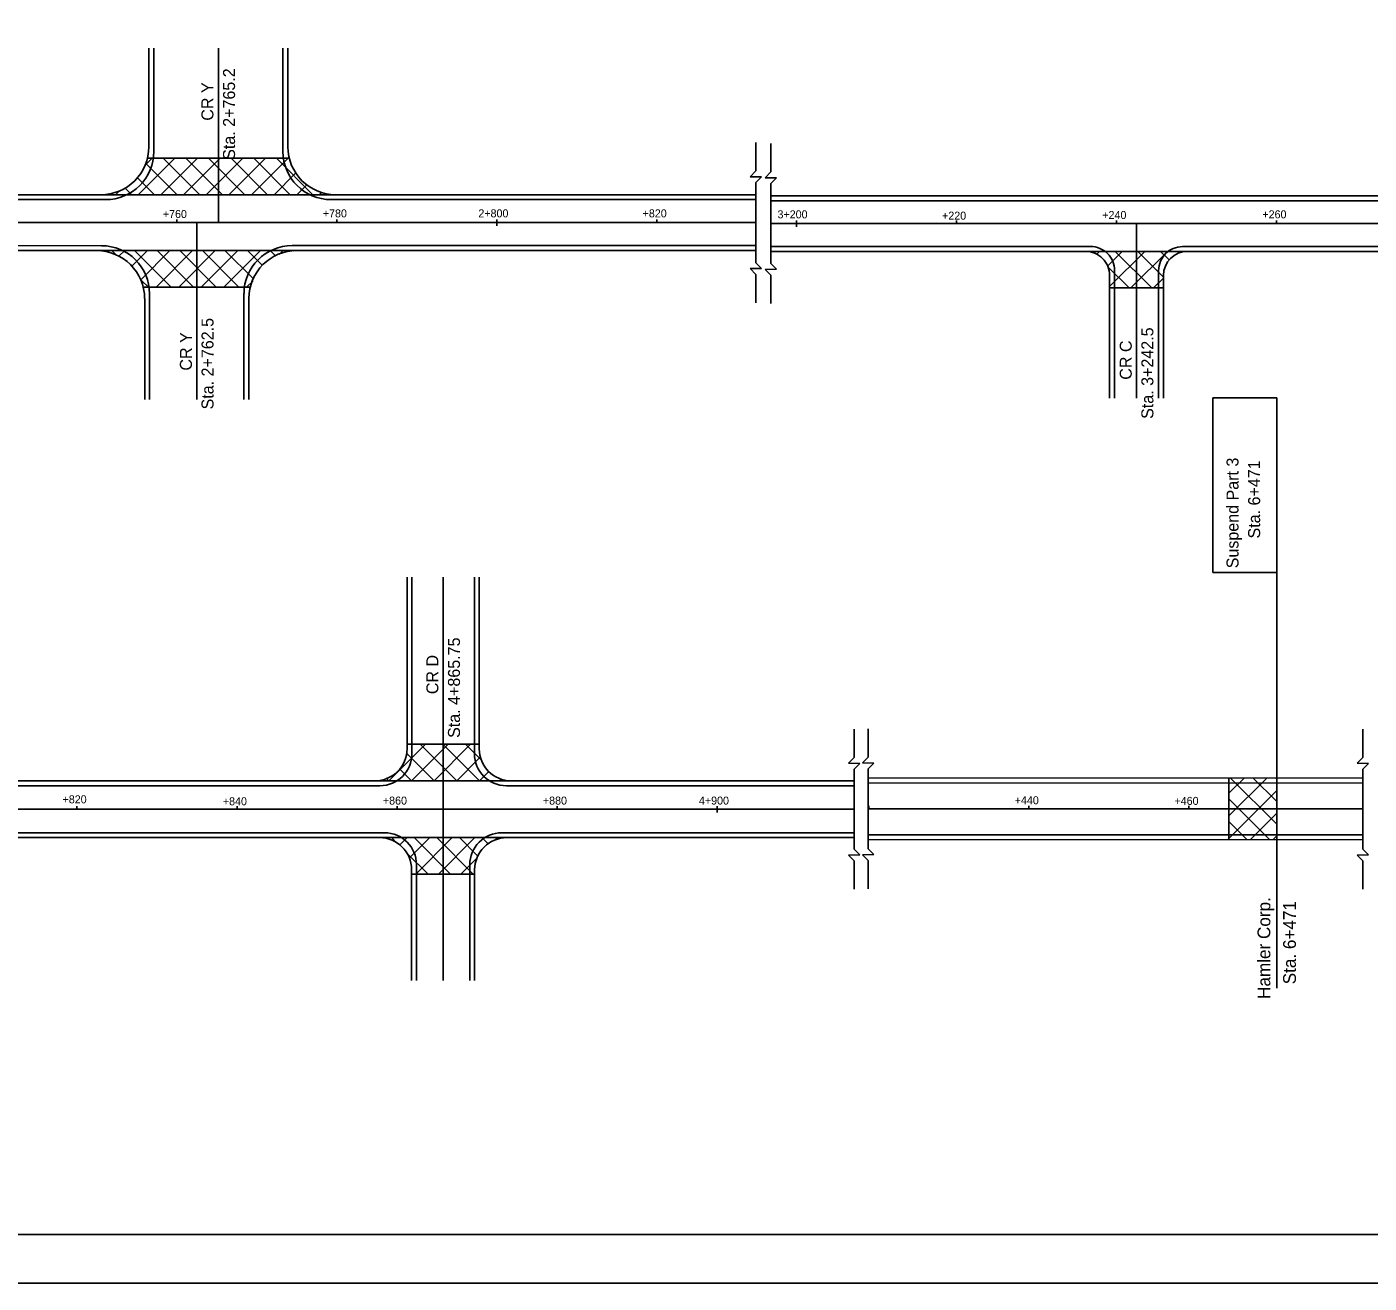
# Model space of a CAD drawing. Extents: x 3 to 683, y -6 to 434.
# Drawn here: x 176.6 to 451.7, y -6.3 to 251.3 of the extents above; entities that cross this region are included whole.
import ezdxf

# ---------------------------------------------------------------- set-up
doc = ezdxf.new("R2010")
doc.units = 0
for name, color, linetype in [('Default', 7, 'Continuous'), ('SH_Border', 7, 'Continuous'), ('SH_Cut_Line', 7, 'Continuous')]:
    doc.layers.add(name, color=color, linetype=linetype)

msp = doc.modelspace()

# ---------------------------------------------------------------- linework, layer by layer
at = {"layer": 'Default'}
for p, q in [((201.56, 226.73), (201.56, 246.92)), ((202.56, 225.73), (202.56, 246.92)), ((215.8, 211.17), (215.8, 246.92)), ((229.05, 225.73), (229.05, 246.92)), ((230.05, 226.73), (230.05, 246.92)), ((325.99, 221.77), (325.99, 227.57)), ((329.03, 221.57), (329.03, 227.37)), ((199.39, 216.89), (206.88, 224.39)), ((200.85, 223), (202.24, 224.39)), ((200.94, 223.29), (207.34, 216.89)), ((201.27, 224.39), (230.34, 224.39)), ((204.03, 216.89), (211.52, 224.39)), ((204.49, 224.39), (211.98, 216.89)), ((208.66, 216.89), (216.16, 224.39)), ((209.13, 224.39), (216.62, 216.89)), ((213.3, 216.89), (220.8, 224.39)), ((213.77, 224.39), (221.26, 216.89)), ((217.94, 216.89), (225.44, 224.39)), ((218.41, 224.39), (225.9, 216.89)), ((222.58, 216.89), (230.08, 224.39)), ((223.05, 224.39), (230.54, 216.89)), ((227.69, 224.39), (235.18, 216.89)), ((199.14, 220.45), (202.7, 216.89)), ((227.22, 216.89), (231.64, 221.31)), ((324.8, 220.58), (325.99, 221.77)), ((324.8, 220.58), (327.15, 220.54)), ((325.99, 219.38), (327.15, 220.54)), ((327.84, 220.38), (329.03, 221.57)), ((327.84, 220.38), (330.19, 220.34)), ((329.03, 219.18), (330.19, 220.34)), ((194.75, 216.89), (195.31, 217.46)), ((196.76, 218.19), (198.06, 216.89)), ((231.86, 216.89), (233.91, 218.93)), ((325.99, 211.17), (325.99, 219.38)), ((329.03, 210.97), (329.03, 219.18)), ((191.71, 216.89), (131.8, 216.89)), ((192.72, 215.89), (131.8, 215.89)), ((191.71, 216.89), (239.89, 216.89)), ((193.19, 217.12), (193.42, 216.89)), ((236.5, 216.89), (236.9, 217.29)), ((325.99, 215.89), (238.89, 215.89)), ((239.81, 216.9), (239.82, 216.89)), ((325.99, 216.89), (239.89, 216.89)), ((414.65, 216.66), (329.03, 216.66)), ((414.65, 215.66), (329.03, 215.66)), ((478.49, 216.66), (414.65, 216.66)), ((478.49, 215.66), (414.65, 215.66)), ((325.99, 211.17), (43.26, 211.17)), ((207.27, 211.17), (207.27, 211.82)), ((211.38, 211.17), (211.38, 174.89)), ((240.08, 211.17), (240.08, 211.82)), ((272.89, 211.17), (272.89, 211.82)), ((272.89, 211.17), (272.89, 210.51)), ((305.7, 211.17), (305.7, 211.82)), ((325.99, 211.17), (325.99, 202.96)), ((478.49, 210.97), (329.03, 210.97)), ((329.03, 210.97), (329.03, 202.76)), ((334.27, 210.97), (334.27, 211.62)), ((334.27, 210.97), (334.27, 210.31)), ((367.08, 210.97), (367.08, 211.62)), ((399.88, 210.97), (399.88, 211.62)), ((403.98, 210.97), (403.98, 175.2)), ((432.69, 210.97), (432.69, 211.62)), ((191.85, 206.45), (131.8, 206.44)), ((325.99, 206.45), (230.9, 206.45)), ((190.85, 205.45), (131.8, 205.44)), ((190.85, 205.45), (231.9, 205.45)), ((191.84, 205.31), (191.97, 205.45)), ((193.96, 205.45), (194.69, 204.72)), ((195.5, 204.33), (196.61, 205.45)), ((198.12, 202.32), (201.25, 205.45)), ((198.6, 205.45), (206.1, 197.95)), ((199.98, 199.53), (205.89, 205.45)), ((203.03, 197.95), (210.53, 205.45)), ((203.24, 205.45), (210.74, 197.95)), ((207.67, 197.95), (215.17, 205.45)), ((207.88, 205.45), (215.38, 197.95)), ((212.31, 197.95), (219.81, 205.45)), ((212.52, 205.45), (220.02, 197.95)), ((216.95, 197.95), (224.45, 205.45)), ((217.16, 205.45), (223.04, 199.57)), ((221.8, 205.45), (224.84, 202.41)), ((226.44, 205.45), (227.61, 204.28)), ((228.27, 204.63), (229.09, 205.45)), ((231.08, 205.45), (231.19, 205.34)), ((325.99, 205.45), (231.9, 205.45)), ((394.55, 206.28), (329.03, 206.27)), ((393.55, 205.28), (329.03, 205.27)), ((393.55, 205.28), (414.65, 205.28)), ((394.96, 205.28), (395.34, 204.9)), ((395.8, 204.66), (396.42, 205.28)), ((398.05, 202.26), (401.06, 205.28)), ((398.47, 198.05), (405.7, 205.28)), ((399.6, 205.28), (407.1, 197.78)), ((402.84, 197.78), (410.34, 205.28)), ((404.24, 205.28), (409.44, 200.08)), ((408.88, 205.28), (410.65, 203.51)), ((414.65, 206.28), (413.42, 206.28)), ((413.52, 205.28), (413.63, 205.17)), ((414.65, 205.28), (414.42, 205.28)), ((478.49, 206.27), (414.65, 206.28)), ((478.49, 205.27), (414.65, 205.28)), ((324.8, 201.76), (327.15, 201.8)), ((324.8, 201.76), (325.99, 200.57)), ((325.99, 202.96), (327.15, 201.8)), ((327.84, 201.55), (330.19, 201.6)), ((327.84, 201.55), (329.03, 200.37)), ((329.03, 202.76), (330.19, 201.6)), ((398.12, 202.12), (402.46, 197.78)), ((399.47, 201.35), (399.47, 175.2)), ((408.5, 201.35), (408.5, 175.2)), ((200.08, 199.33), (201.46, 197.95)), ((221.59, 197.95), (222.91, 199.27)), ((325.99, 200.57), (325.99, 194.76)), ((329.03, 200.37), (329.03, 194.56)), ((398.47, 200.35), (398.47, 175.2)), ((407.48, 197.78), (409.45, 199.74)), ((409.5, 200.35), (409.5, 175.2)), ((200.41, 197.95), (222.34, 197.95)), ((200.7, 195.6), (200.7, 174.89)), ((201.7, 196.6), (201.7, 174.89)), ((221.05, 196.61), (221.05, 174.89)), ((222.05, 195.61), (222.05, 174.89)), ((398.47, 197.78), (409.5, 197.78)), ((419.61, 139.42), (419.64, 175.22)), ((432.75, 175.22), (419.63, 175.22)), ((432.75, 114.82), (432.75, 175.22)), ((254.47, 103.28), (254.47, 138.46)), ((255.47, 102.28), (255.47, 138.46)), ((261.87, 55.78), (261.87, 138.46)), ((268.27, 102.28), (268.27, 138.46)), ((269.27, 103.28), (269.27, 138.46)), ((432.74, 139.42), (419.61, 139.42)), ((432.75, 127.76), (432.75, 90.97)), ((346.12, 101.5), (346.12, 107.3)), ((348.97, 101.57), (348.97, 107.37)), ((450.36, 101.5), (450.36, 107.3)), ((250.73, 96.72), (258.23, 104.22)), ((254.43, 102.33), (260.03, 96.72)), ((254.47, 104.22), (269.27, 104.22)), ((255.37, 96.72), (262.87, 104.22)), ((257.18, 104.22), (264.67, 96.72)), ((260.01, 96.72), (267.51, 104.22)), ((261.82, 104.22), (269.31, 96.72)), ((266.46, 104.22), (269.81, 100.86)), ((252.92, 99.2), (255.39, 96.72)), ((264.65, 96.72), (269.49, 101.55)), ((344.94, 100.31), (346.12, 101.5)), ((344.94, 100.31), (347.28, 100.27)), ((346.12, 99.11), (347.28, 100.27)), ((346.12, 90.9), (346.12, 99.11)), ((347.79, 100.38), (348.97, 101.57)), ((347.79, 100.38), (350.13, 100.34)), ((348.97, 99.18), (350.13, 100.34)), ((348.97, 90.97), (348.97, 99.18)), ((449.18, 100.31), (450.36, 101.5)), ((449.18, 100.31), (451.52, 100.27)), ((450.36, 99.11), (451.52, 100.27)), ((450.36, 90.9), (450.36, 99.11)), ((228.16, 96.72), (155.17, 96.72)), ((247.91, 96.72), (228.16, 96.72)), ((247.91, 96.72), (275.83, 96.72)), ((250.16, 97.32), (250.75, 96.72)), ((269.29, 96.72), (271.28, 98.7)), ((273.58, 97.09), (273.95, 96.72)), ((273.93, 96.72), (274.2, 96.99)), ((346.12, 96.72), (275.83, 96.72)), ((450.36, 97.32), (348.97, 97.27)), ((450.36, 96.32), (348.97, 96.27)), ((422.91, 84.63), (422.91, 97.31)), ((422.91, 89.52), (430.69, 97.3)), ((422.91, 94.16), (426.05, 97.3)), ((423.27, 97.3), (432.75, 87.82)), ((427.9, 97.3), (432.75, 92.45)), ((432.54, 97.3), (432.75, 97.09)), ((228.16, 95.72), (155.17, 95.72)), ((248.91, 95.72), (228.16, 95.72)), ((346.12, 95.72), (274.83, 95.72)), ((422.65, 84.63), (432.75, 94.72)), ((346.12, 90.9), (155.17, 90.9)), ((186.82, 90.9), (186.82, 91.55)), ((219.63, 90.9), (219.63, 91.55)), ((252.44, 90.9), (252.44, 91.55)), ((285.24, 90.9), (285.24, 91.55)), ((318.05, 90.9), (318.05, 91.55)), ((318.05, 90.9), (318.05, 90.24)), ((346.12, 90.9), (346.12, 82.69)), ((348.97, 90.97), (348.97, 82.76)), ((450.36, 90.97), (348.97, 90.97)), ((349.09, 90.97), (349.09, 91.62)), ((381.9, 90.97), (381.9, 91.62)), ((414.71, 90.97), (414.71, 91.62)), ((422.91, 93.02), (431.3, 84.63)), ((432.75, 84.63), (432.75, 90.97)), ((432.75, 90.97), (432.75, 54.18)), ((450.36, 90.9), (450.36, 82.69)), ((422.91, 88.38), (426.66, 84.63)), ((427.29, 84.63), (432.75, 90.08)), ((228.19, 86.08), (155.17, 86.08)), ((249.85, 86.07), (228.16, 86.07)), ((346.12, 86.07), (273.89, 86.07)), ((450.36, 85.62), (348.97, 85.66)), ((431.93, 84.63), (432.75, 85.44)), ((228.19, 85.08), (155.17, 85.08)), ((248.85, 85.07), (228.16, 85.07)), ((248.85, 85.07), (274.89, 85.07)), ((249.71, 84.96), (249.83, 85.07)), ((251.27, 85.07), (252.4, 83.94)), ((252.93, 83.54), (254.47, 85.07)), ((254.98, 80.95), (259.11, 85.07)), ((255.91, 85.07), (263.41, 77.58)), ((256.25, 77.58), (263.75, 85.07)), ((260.55, 85.07), (268.05, 77.58)), ((260.89, 77.58), (268.39, 85.07)), ((265.19, 85.07), (268.99, 81.28)), ((269.83, 85.07), (271.02, 83.88)), ((272.58, 84.63), (273.03, 85.07)), ((274.47, 85.07), (274.49, 85.05)), ((346.12, 85.07), (274.89, 85.07)), ((346.12, 82.69), (347.28, 81.53)), ((450.36, 84.62), (348.97, 84.66)), ((348.97, 82.76), (350.13, 81.6)), ((450.36, 82.69), (451.52, 81.53)), ((254.56, 81.78), (258.77, 77.58)), ((265.53, 77.58), (268.65, 80.7)), ((344.94, 81.48), (347.28, 81.53)), ((344.94, 81.48), (346.12, 80.3)), ((346.12, 80.3), (346.12, 74.49)), ((347.79, 81.56), (350.13, 81.6)), ((347.79, 81.56), (348.97, 80.37)), ((348.97, 80.37), (348.97, 74.56)), ((449.18, 81.48), (451.52, 81.53)), ((449.18, 81.48), (450.36, 80.3)), ((450.36, 80.3), (450.36, 74.49)), ((255.41, 55.78), (255.41, 78.51)), ((255.41, 77.58), (268.32, 77.58)), ((256.41, 55.78), (256.41, 79.51)), ((267.32, 55.78), (267.32, 79.51)), ((268.32, 55.78), (268.32, 78.51))]:
    msp.add_line(p, q, dxfattribs=at)
for centre, radius, start, end in [((191.71, 226.73), 9.84, 269.9995, 360), ((192.72, 225.73), 9.84, 269.9981, 0), ((238.89, 225.73), 9.84, 180, 269.9981), ((239.89, 226.73), 9.84, 180, 269.9982), ((191.85, 196.6), 9.84, 0, 89.9997), ((230.9, 196.61), 9.84, 90.001, 180), ((190.85, 195.6), 9.84, 0, 89.9992), ((231.9, 195.61), 9.84, 90.0031, 180), ((393.55, 200.35), 4.92, 0, 90.0005), ((394.55, 201.35), 4.92, 0, 90.0019), ((413.42, 201.35), 4.92, 90.0031, 180), ((414.42, 200.35), 4.92, 90.0007, 180), ((247.91, 103.28), 6.56, 270, 0), ((248.91, 102.28), 6.56, 270, 0), ((274.83, 102.28), 6.56, 180, 270), ((275.83, 103.28), 6.56, 180, 270), ((249.85, 79.51), 6.56, 0, 89.9974), ((273.88, 79.51), 6.56, 89.9972, 180), ((248.85, 78.51), 6.56, 0, 89.9987), ((274.89, 78.51), 6.56, 89.9989, 180)]:
    msp.add_arc(centre, radius, start, end, dxfattribs=at)
at = {"layer": 'SH_Border'}
msp.add_lwpolyline([(32.89, 423.72), (672.89, 423.72), (672.89, 3.72), (32.89, 3.72)], close=True, dxfattribs=at)
at = {"layer": 'SH_Cut_Line'}
msp.add_lwpolyline([(2.89, -6.28), (682.89, -6.28), (682.89, 433.72), (2.89, 433.72)], close=True, dxfattribs=at)

# ---------------------------------------------------------------- texts
at = {"layer": 'Default'}
for s, height, p in [('Sta. 2+765.2', 2.4606, (219.22, 224.05)), ('CR Y', 2.461, (214.79, 232.07)), ('Sta. 2+762.5', 2.4606, (214.81, 172.87)), ('CR Y', 2.461, (210.38, 180.83)), ('Sta. 3+242.5', 2.4606, (407.43, 170.93)), ('CR C', 2.461, (403, 178.96)), ('Suspend Part 3', 2.4606, (424.88, 140.3)), ('Sta. 6+471', 2.461, (429.31, 146.41)), ('Sta. 4+865.75', 2.4606, (265.32, 105.52)), ('CR D', 2.461, (260.89, 114.49)), ('Hamler Corp.', 2.6247, (431.4, 52)), ('Sta. 6+471', 2.625, (436.65, 55))]:
    msp.add_text(s, height=height, rotation=90, dxfattribs=at).set_placement(p)
for s, p in [('+760', (204.42, 212.12)), ('+780', (237.21, 212.25)), ('2+800', (269.09, 212.25)), ('+820', (302.75, 212.25)), ('3+200', (330.4, 212.05)), ('+220', (364.12, 211.78)), ('+240', (396.96, 211.92)), ('+260', (429.77, 212.05)), ('+820', (183.87, 92.11)), ('+440', (379.01, 91.92)), ('+840', (216.72, 91.71)), ('+860', (249.52, 91.85)), ('+880', (282.31, 91.85)), ('4+900', (314.29, 91.85)), ('+460', (411.75, 91.79))]:
    msp.add_text(s, height=1.64, dxfattribs=at).set_placement(p)

doc.saveas('drawing.dxf')
